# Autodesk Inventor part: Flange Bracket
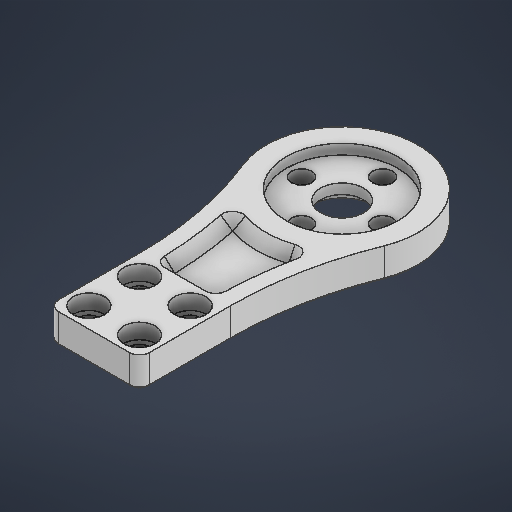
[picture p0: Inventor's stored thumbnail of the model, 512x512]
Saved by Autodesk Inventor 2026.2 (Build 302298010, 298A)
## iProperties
Created: 2026-05
Part Number: Flange Bracket
Material: 일반
Document SubType Name: Modeling
Designer: work
Density: 1 g/cm^3
Appearance: 기본값
Author: work
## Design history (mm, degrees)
sketch "스케치1"
  geometry: L1 (-5, 5)-(5, 5); L2 (5, 5)-(5, -5); L3 (5, -5)-(-5, -5); L4 (-5, -5)-(-5, 5); L5 (-5, 5)-(5, -5); L6 (5, 5)-(-5, -5); L7 (-9, 9)-(9, 9); L8 (9, 9)-(9, -9); L9 (9, -9)-(-9, -9); L10 (-9, -9)-(-9, 9); L11 (-9, 9)-(9, -9); L12 (9, 9)-(-9, -9); L13 (0, -40)-(8, -40); L14 (0, -40)-(0, 0); L15 (0, -40)-(0, -32); L16 (0, -40)-(-8, -40); L17 (0, -40)-(0, -48); L18 (6, -9)-(6, 9); C1 r 2 at (5, 5); C2 r 2 at (5, -5); C3 r 2 at (-5, -5); C4 r 2 at (-5, 5); C5 r 11 at (0, -40); C6 r 4.25 at (0, -40); C7 r 2 at (8, -40); C8 r 2 at (0, -32); C9 r 2 at (-8, -40); C10 r 2 at (0, -48); A1 r 15 centre (0, -40) between (13.917, -34.403) and (8.485, -27.63); A2 r 68.083 centre (77.083, -9) between (9, -9) and (13.917, -34.403); A3 r 68.083 centre (-77.083, -9) between (-13.917, -34.403) and (-9, -9); A4 r 71.083 centre (77.083, -9) between (6, -9) and (8.485, -27.63); A5 r 71.083 centre (-77.083, -9) between (-8.485, -27.63) and (-6, -9); 3 further points
  constraints: 36 end point, 15 centre point, 10 coincident, 10 point on circle, 5 symmetric about line, 4 midpoint, 4 parallel, 3 horizontal, 3 perpendicular, 3 tangent, 2 point on line, 1 concentric, 1 vertical, 23 other
  dimensions: "d0" = 10 distance of L2.end L3.end; "d1" = 10 distance of L1.end L2.end; "d2" = 4 diameter of C1; "d3" = 4 diameter of C2; "d4" = 4 diameter of C3; "d5" = 4 diameter of C4; "d6" = 18 distance of L8.end L9.end; "d7" = 18 distance of L7.end L8.end; "d8" = 22 diameter of C5; "d9" = 8 distance of L13.start L13.end; "d10" = 8.5 diameter of C6; "d11" = 40 distance of L14.start L14.end; "d12" = 4 diameter of C7; "d15" = 360 deg dimension on L14.start L13.end (derived); "d17" = 30 diameter of A1; "d18" = 3 distance between parallel lines of L8 L18
  node "스케치 - 원형 패턴1" dims "d15" = 360 deg (derived)
extrude "돌출1" new body sketch "스케치1" distance "d19" = 6; taper "d20" = 0 deg
extrude "돌출2" join sketch "스케치1" distance "d21" = 4; taper "d22" = 0 deg
fillet "모깎기1" dims "d23" = 2
chamfer "모따기1" distance "d24" = 2; stored, may be unused: second distance "d25" = 2, angle "d26" = 45 deg
sketch "스케치2"
  geometry: C1 r 2 at (5, 5) reference; C2 r 2 at (5, -5) reference; C3 r 2 at (-5, 5) reference; C4 r 2 at (-5, -5) reference; 5 further points
  constraints: 4 coincident
hole "구멍1" sketch "스케치2" at (5, 5), (5, -5), (-5, 5), (-5, -5) diameter "d27" = 4; stored, may be unused: countersink angle "d31" = 90 deg, drill point angle "d33" = 118 deg; dims "d28" = 6, "d29" = 6.2, "d30" = 3, "d32" = 8
chamfer "모따기2" distance "d34" = 0.5; stored, may be unused: second distance "d35" = 2, angle "d36" = 45 deg
node "솔리드1"
feature "A9D066F2-1C7D-4E18-AEED-F7BC21143FA4" dims "d27" = 4, "d28" = 6, "d29" = 6.2, "d30" = 3, "d31" = 90 deg, "d32" = 8, "d33" = 118 deg
